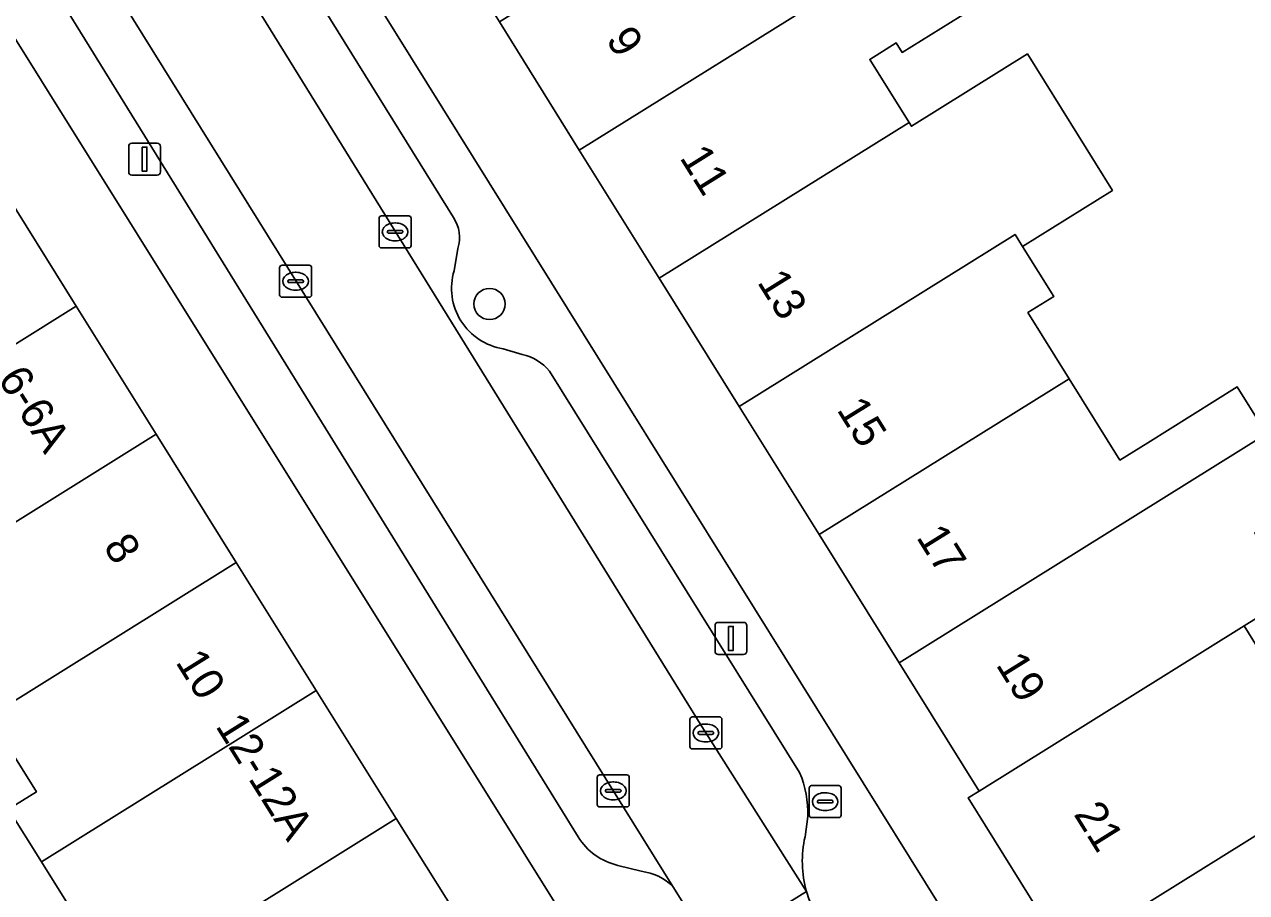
# Model space of a CAD drawing. Extents: x 159279 to 160377, y 384531 to 385888.
# Drawn here: x 159890.84 to 159929.07, y 385050.51 to 385077.67 of the extents above; entities that cross this region are included whole.
import ezdxf

# ---------------------------------------------------------------- set-up
doc = ezdxf.new("R2010")
doc.units = 0
for name, color, linetype in [('IMGEO_Boom', 7, 'Continuous'), ('IMGEO_Brandkraan', 7, 'Continuous'), ('IMGEO_Erf', 7, 'Continuous'), ('IMGEO_Kolk', 7, 'Continuous'), ('IMGEO_Lichtmast', 7, 'Continuous'), ('IMGEO_Pand', 7, 'Continuous'), ('IMGEO_Pand_nummerreeks', 7, 'Continuous'), ('IMGEO_Parkeervlak_open', 7, 'Continuous'), ('IMGEO_Rijbaan_lokaal_open', 7, 'Continuous'), ('IMGEO_Voetpad_open', 7, 'Continuous')]:
    doc.layers.add(name, color=color, linetype=linetype)

msp = doc.modelspace()

# ---------------------------------------------------------------- linework, layer by layer
at = {"layer": 'IMGEO_Boom'}
msp.add_circle((159905.388, 385068.924), 0.489, dxfattribs=at)
at = {"layer": 'IMGEO_Brandkraan'}
for p, q in [((159915.385, 385052.93), (159915.385, 385053.782)), ((159915.46, 385053.856), (159916.312, 385053.856)), ((159916.386, 385053.782), (159916.386, 385052.93)), ((159915.644, 385053.35), (159915.644, 385053.362)), ((159916.082, 385053.313), (159915.684, 385053.313)), ((159915.687, 385053.399), (159916.085, 385053.399)), ((159915.873, 385053.636), (159915.898, 385053.636)), ((159916.128, 385053.362), (159916.128, 385053.35)), ((159915.896, 385053.076), (159915.871, 385053.076)), ((159916.312, 385052.856), (159915.46, 385052.856))]:
    msp.add_line(p, q, dxfattribs=at)
for points in [[(159915.385, 385052.93), (159915.385, 385053.782)], [(159915.46, 385053.856), (159916.312, 385053.856)], [(159916.386, 385053.782), (159916.386, 385052.93)], [(159916.312, 385052.856), (159915.46, 385052.856)]]:
    msp.add_lwpolyline(points, dxfattribs=at)
for centre, radius, start, end in [((159915.462, 385053.78), 0.0765, 91.552, 178.448), ((159915.462, 385053.78), 0.0765, 91.552, 178.448), ((159916.31, 385053.78), 0.0765, 1.552, 88.448), ((159916.31, 385053.78), 0.0765, 1.552, 88.448), ((159915.684, 385053.359), 0.0403, 85.8775, 175.7526), ((159915.681, 385053.349), 0.0366, 178.938, 274.7102), ((159916.085, 385053.356), 0.043, 264.8664, 352.4533), ((159916.089, 385053.361), 0.0386, 1.7309, 96.639), ((159915.462, 385052.932), 0.0765, 181.552, 268.448), ((159915.462, 385052.932), 0.0765, 181.552, 268.448), ((159916.31, 385052.932), 0.0765, 271.552, 358.448), ((159916.31, 385052.932), 0.0765, 271.552, 358.448)]:
    msp.add_arc(centre, radius, start, end, dxfattribs=at)
for centre, major_axis, ratio, start_param, end_param in [((159915.872, 385053.356), (-0.387, 0.002), 0.722429, 4.712389, 7.853982), ((159915.897, 385053.356), (-0.39, 0.002), 0.717154, 1.570796, 4.712389)]:
    msp.add_ellipse(centre, major_axis=major_axis, ratio=ratio, start_param=start_param, end_param=end_param, dxfattribs=at)
at = {"layer": 'IMGEO_Erf'}
msp.add_lwpolyline([(159910.697, 385069.73), (159908.196, 385073.741), (159905.695, 385077.752), (159903.193, 385081.764), (159900.797, 385085.607), (159900.692, 385085.775), (159899.904, 385085.283), (159899.772, 385085.494), (159898.904, 385084.953), (159897.291, 385087.541), (159898.155, 385088.079), (159897.319, 385089.42), (159895.629, 385088.366), (159920.97, 385047.69), (159923.122, 385049.031), (159920.357, 385053.472), (159920.701, 385053.686), (159918.2, 385057.697), (159915.699, 385061.708), (159913.198, 385065.719)], close=True, dxfattribs=at)
for points in [[(159936.519, 385003.628), (159888.362, 385080.722), (159886.834, 385079.767), (159887.125, 385079.301), (159887.917, 385079.795), (159889.478, 385077.298), (159888.696, 385076.809), (159889.575, 385075.404), (159888.705, 385074.86), (159889.956, 385072.859), (159892.459, 385068.853), (159894.962, 385064.848), (159897.466, 385060.841), (159899.969, 385056.836), (159902.473, 385052.829), (159904.977, 385048.823)], [(159921.316, 385078.681), (159918.293, 385076.795), (159918.11, 385077.091), (159917.281, 385076.574), (159918.51, 385074.602), (159918.583, 385074.485), (159922.21, 385076.747), (159924.873, 385072.478), (159922.061, 385070.723), (159923.037, 385069.158), (159922.228, 385068.654), (159923.518, 385066.584), (159925.104, 385064.041), (159925.975, 385064.584), (159928.777, 385066.331), (159929.693, 385064.863)], [(159892.655, 385049.419), (159891.372, 385051.471), (159890.343, 385053.118), (159891.214, 385053.662), (159889.74, 385056.02), (159888.532, 385057.953), (159887.653, 385057.404), (159886.356, 385059.478), (159885.234, 385061.273), (159886.111, 385061.821), (159884.73, 385064.031), (159883.458, 385066.066), (159882.603, 385065.531), (159881.388, 385067.474), (159881.7, 385067.706), (159883.088, 385068.573), (159883.016, 385068.688), (159880.922, 385072.039), (159883.95, 385073.931), (159882.137, 385076.832), (159880.13, 385075.578), (159872.046, 385062.696), (159880.878, 385049.064)], [(159930.536, 385059.818), (159928.995, 385058.857), (159930.589, 385056.28)]]:
    msp.add_lwpolyline(points, dxfattribs=at)
at = {"layer": 'IMGEO_Kolk'}
for p, q in [((159902.009, 385071.68), (159902.861, 385071.68)), ((159901.934, 385070.754), (159901.934, 385071.606)), ((159902.422, 385071.46), (159902.447, 385071.46)), ((159902.935, 385071.606), (159902.935, 385070.754)), ((159902.193, 385071.174), (159902.193, 385071.186)), ((159902.631, 385071.137), (159902.233, 385071.137)), ((159902.236, 385071.223), (159902.634, 385071.223)), ((159902.445, 385070.9), (159902.42, 385070.9)), ((159902.677, 385071.186), (159902.677, 385071.174)), ((159902.861, 385070.68), (159902.009, 385070.68)), ((159898.898, 385070.135), (159899.75, 385070.135)), ((159898.823, 385069.209), (159898.823, 385070.061)), ((159899.311, 385069.915), (159899.336, 385069.915)), ((159899.824, 385070.061), (159899.824, 385069.209)), ((159899.082, 385069.629), (159899.082, 385069.641)), ((159899.52, 385069.592), (159899.122, 385069.592)), ((159899.125, 385069.678), (159899.523, 385069.678)), ((159899.334, 385069.355), (159899.309, 385069.355)), ((159899.566, 385069.641), (159899.566, 385069.629)), ((159899.75, 385069.135), (159898.898, 385069.135)), ((159911.729, 385056.004), (159912.581, 385056.004)), ((159911.654, 385055.078), (159911.654, 385055.93)), ((159912.142, 385055.784), (159912.167, 385055.784)), ((159912.655, 385055.93), (159912.655, 385055.078)), ((159911.913, 385055.498), (159911.913, 385055.51)), ((159912.351, 385055.461), (159911.953, 385055.461)), ((159911.956, 385055.547), (159912.354, 385055.547)), ((159912.165, 385055.224), (159912.14, 385055.224)), ((159912.397, 385055.51), (159912.397, 385055.498)), ((159912.581, 385055.004), (159911.729, 385055.004)), ((159908.758, 385053.266), (159908.758, 385054.118)), ((159908.833, 385054.192), (159909.685, 385054.192)), ((159909.759, 385054.118), (159909.759, 385053.266)), ((159909.017, 385053.686), (159909.017, 385053.698)), ((159909.455, 385053.649), (159909.057, 385053.649)), ((159909.06, 385053.735), (159909.458, 385053.735)), ((159909.246, 385053.972), (159909.271, 385053.972)), ((159909.501, 385053.698), (159909.501, 385053.686)), ((159909.269, 385053.412), (159909.244, 385053.412)), ((159909.685, 385053.192), (159908.833, 385053.192))]:
    msp.add_line(p, q, dxfattribs=at)
for points in [[(159902.009, 385071.68), (159902.861, 385071.68)], [(159901.934, 385070.754), (159901.934, 385071.606)], [(159902.935, 385071.606), (159902.935, 385070.754)], [(159902.861, 385070.68), (159902.009, 385070.68)], [(159898.898, 385070.135), (159899.75, 385070.135)], [(159898.823, 385069.209), (159898.823, 385070.061)], [(159899.824, 385070.061), (159899.824, 385069.209)], [(159899.75, 385069.135), (159898.898, 385069.135)], [(159911.729, 385056.004), (159912.581, 385056.004)], [(159911.654, 385055.078), (159911.654, 385055.93)], [(159912.655, 385055.93), (159912.655, 385055.078)], [(159912.581, 385055.004), (159911.729, 385055.004)], [(159908.758, 385053.266), (159908.758, 385054.118)], [(159908.833, 385054.192), (159909.685, 385054.192)], [(159909.759, 385054.118), (159909.759, 385053.266)], [(159909.685, 385053.192), (159908.833, 385053.192)]]:
    msp.add_lwpolyline(points, dxfattribs=at)
for centre, radius, start, end in [((159902.011, 385071.604), 0.0765, 91.552, 178.448), ((159902.011, 385071.604), 0.0765, 91.552, 178.448), ((159902.859, 385071.604), 0.0765, 1.552, 88.448), ((159902.859, 385071.604), 0.0765, 1.552, 88.448), ((159902.233, 385071.183), 0.0403, 85.8775, 175.7526), ((159902.23, 385071.173), 0.0366, 178.938, 274.7102), ((159902.634, 385071.18), 0.043, 264.8664, 352.4533), ((159902.638, 385071.185), 0.0386, 1.7309, 96.639), ((159902.011, 385070.756), 0.0765, 181.552, 268.448), ((159902.011, 385070.756), 0.0765, 181.552, 268.448), ((159902.859, 385070.756), 0.0765, 271.552, 358.448), ((159902.859, 385070.756), 0.0765, 271.552, 358.448), ((159898.9, 385070.059), 0.0765, 91.552, 178.448), ((159898.9, 385070.059), 0.0765, 91.552, 178.448), ((159899.748, 385070.059), 0.0765, 1.552, 88.448), ((159899.748, 385070.059), 0.0765, 1.552, 88.448), ((159899.122, 385069.638), 0.0403, 85.8775, 175.7526), ((159899.119, 385069.628), 0.0366, 178.938, 274.7102), ((159899.523, 385069.635), 0.043, 264.8664, 352.4533), ((159899.527, 385069.64), 0.0386, 1.7309, 96.639), ((159898.9, 385069.211), 0.0765, 181.552, 268.448), ((159898.9, 385069.211), 0.0765, 181.552, 268.448), ((159899.748, 385069.211), 0.0765, 271.552, 358.448), ((159899.748, 385069.211), 0.0765, 271.552, 358.448), ((159911.731, 385055.928), 0.0765, 91.552, 178.448), ((159911.731, 385055.928), 0.0765, 91.552, 178.448), ((159912.579, 385055.928), 0.0765, 1.552, 88.448), ((159912.579, 385055.928), 0.0765, 1.552, 88.448), ((159911.953, 385055.507), 0.0403, 85.8775, 175.7526), ((159911.95, 385055.497), 0.0366, 178.938, 274.7102), ((159912.354, 385055.504), 0.043, 264.8664, 352.4533), ((159912.358, 385055.509), 0.0386, 1.7309, 96.639), ((159911.731, 385055.08), 0.0765, 181.552, 268.448), ((159911.731, 385055.08), 0.0765, 181.552, 268.448), ((159912.579, 385055.08), 0.0765, 271.552, 358.448), ((159912.579, 385055.08), 0.0765, 271.552, 358.448), ((159908.835, 385054.116), 0.0765, 91.552, 178.448), ((159908.835, 385054.116), 0.0765, 91.552, 178.448), ((159909.683, 385054.116), 0.0765, 1.552, 88.448), ((159909.683, 385054.116), 0.0765, 1.552, 88.448), ((159909.057, 385053.695), 0.0403, 85.8775, 175.7526), ((159909.054, 385053.685), 0.0366, 178.938, 274.7102), ((159909.458, 385053.692), 0.043, 264.8664, 352.4533), ((159909.462, 385053.697), 0.0386, 1.7309, 96.639), ((159908.835, 385053.268), 0.0765, 181.552, 268.448), ((159908.835, 385053.268), 0.0765, 181.552, 268.448), ((159909.683, 385053.268), 0.0765, 271.552, 358.448), ((159909.683, 385053.268), 0.0765, 271.552, 358.448)]:
    msp.add_arc(centre, radius, start, end, dxfattribs=at)
for centre, major_axis, ratio, start_param, end_param in [((159902.421, 385071.18), (-0.387, 0.002), 0.722429, 4.712389, 7.853982), ((159902.446, 385071.18), (-0.39, 0.002), 0.717154, 1.570796, 4.712389), ((159899.31, 385069.635), (-0.387, 0.002), 0.722429, 4.712389, 7.853982), ((159899.335, 385069.635), (-0.39, 0.002), 0.717154, 1.570796, 4.712389), ((159912.141, 385055.504), (-0.387, 0.002), 0.722429, 4.712389, 7.853982), ((159912.166, 385055.504), (-0.39, 0.002), 0.717154, 1.570796, 4.712389), ((159909.245, 385053.692), (-0.387, 0.002), 0.722429, 4.712389, 7.853982), ((159909.27, 385053.692), (-0.39, 0.002), 0.717154, 1.570796, 4.712389)]:
    msp.add_ellipse(centre, major_axis=major_axis, ratio=ratio, start_param=start_param, end_param=end_param, dxfattribs=at)
at = {"layer": 'IMGEO_Lichtmast'}
for p, q in [((159894.202, 385073.956), (159894.992, 385073.956)), ((159894.992, 385073.956), (159894.202, 385073.956)), ((159894.102, 385073.056), (159894.102, 385073.856)), ((159894.102, 385073.856), (159894.102, 385073.056)), ((159895.092, 385073.856), (159895.092, 385073.056)), ((159895.092, 385073.056), (159895.092, 385073.856)), ((159894.992, 385072.956), (159894.202, 385072.956)), ((159894.202, 385072.956), (159894.992, 385072.956)), ((159912.442, 385058.063), (159912.442, 385058.863)), ((159912.442, 385058.863), (159912.442, 385058.063)), ((159912.542, 385058.963), (159913.332, 385058.963)), ((159913.332, 385058.963), (159912.542, 385058.963)), ((159913.432, 385058.863), (159913.432, 385058.063)), ((159913.432, 385058.063), (159913.432, 385058.863)), ((159913.332, 385057.963), (159912.542, 385057.963)), ((159912.542, 385057.963), (159913.332, 385057.963))]:
    msp.add_line(p, q, dxfattribs=at)
for points in [[(159894.522, 385073.831), (159894.672, 385073.831), (159894.672, 385073.081), (159894.522, 385073.081), (159894.522, 385073.831)], [(159912.862, 385058.838), (159913.012, 385058.838), (159913.012, 385058.088), (159912.862, 385058.088), (159912.862, 385058.838)]]:
    msp.add_lwpolyline(points, dxfattribs=at)
for centre, start, end in [((159894.202, 385073.856), 90, 180), ((159894.202, 385073.856), 90, 180), ((159894.992, 385073.856), 0, 90), ((159894.992, 385073.856), 360, 90), ((159894.202, 385073.056), 180, 270), ((159894.202, 385073.056), 180, 270), ((159894.992, 385073.056), 270, 0), ((159894.992, 385073.056), 270, 0), ((159912.542, 385058.863), 90, 180), ((159912.542, 385058.863), 90, 180), ((159913.332, 385058.863), 0, 90), ((159913.332, 385058.863), 360, 90), ((159912.542, 385058.063), 180, 270), ((159912.542, 385058.063), 180, 270), ((159913.332, 385058.063), 270, 0), ((159913.332, 385058.063), 270, 0)]:
    msp.add_arc(centre, 0.1, start, end, dxfattribs=at)
at = {"layer": 'IMGEO_Pand'}
for points in [[(159905.695, 385077.752), (159908.196, 385073.741), (159916.838, 385079.13), (159915.82, 385080.763), (159915, 385080.252), (159913.517, 385082.63)], [(159916.838, 385079.13), (159908.196, 385073.741), (159910.697, 385069.73), (159918.51, 385074.602), (159917.281, 385076.574), (159918.11, 385077.091), (159918.293, 385076.795), (159921.316, 385078.681), (159921.132, 385078.976), (159921.083, 385079.055), (159919.86, 385081.015)], [(159921.826, 385071.099), (159922.061, 385070.723), (159924.873, 385072.478), (159922.21, 385076.747), (159918.583, 385074.485), (159918.51, 385074.602), (159910.697, 385069.73), (159913.198, 385065.719)], [(159892.459, 385068.853), (159889.956, 385072.859), (159883.088, 385068.573), (159881.7, 385067.706), (159881.388, 385067.474), (159882.603, 385065.531), (159883.458, 385066.066), (159884.73, 385064.031)], [(159923.518, 385066.584), (159922.228, 385068.654), (159923.037, 385069.158), (159922.061, 385070.723), (159921.826, 385071.099), (159913.198, 385065.719), (159915.699, 385061.708)], [(159894.962, 385064.848), (159892.459, 385068.853), (159884.73, 385064.031), (159886.111, 385061.821), (159885.234, 385061.273), (159886.356, 385059.478)], [(159929.693, 385064.863), (159928.777, 385066.331), (159925.975, 385064.584), (159925.104, 385064.041), (159923.518, 385066.584), (159915.699, 385061.708), (159918.2, 385057.697)], [(159886.356, 385059.478), (159887.653, 385057.404), (159888.532, 385057.953), (159889.74, 385056.02), (159897.466, 385060.841), (159894.962, 385064.848)], [(159930.536, 385059.818), (159929.322, 385061.766), (159930.979, 385062.8), (159929.693, 385064.863), (159918.2, 385057.697), (159920.701, 385053.686), (159928.995, 385058.857)], [(159899.969, 385056.836), (159897.466, 385060.841), (159889.74, 385056.02), (159891.214, 385053.662), (159890.343, 385053.118), (159891.372, 385051.471)], [(159932.027, 385053.956), (159931.577, 385054.683), (159930.589, 385056.28), (159928.995, 385058.857), (159920.701, 385053.686), (159920.357, 385053.472), (159923.122, 385049.031), (159923.401, 385048.583), (159931.872, 385053.86)], [(159891.372, 385051.471), (159892.655, 385049.419), (159893.516, 385049.958), (159894.738, 385048.003), (159902.473, 385052.829), (159899.969, 385056.836)], [(159932.705, 385050.93), (159933.567, 385051.467), (159936.373, 385053.215), (159935.086, 385055.282), (159934.826, 385055.699), (159932.027, 385053.956), (159931.872, 385053.86), (159923.401, 385048.583), (159923.69, 385048.119), (159926.445, 385043.693), (159926.789, 385043.908), (159934.649, 385048.811), (159934.454, 385049.124), (159934.004, 385048.844)], [(159904.977, 385048.823), (159902.473, 385052.829), (159894.738, 385048.003), (159896.192, 385045.676), (159895.28, 385045.106), (159896.329, 385043.428)]]:
    msp.add_lwpolyline(points, close=True, dxfattribs=at)
at = {"layer": 'IMGEO_Parkeervlak_open'}
for points in [[(159893.204, 385086.133), (159912.027, 385055.709), (159915.303, 385050.54)], [(159904.257, 385071.628), (159896.191, 385084.632)], [(159911.126, 385050.697), (159890.937, 385083.152)], [(159891.126, 385079.816), (159908.159, 385052.253)], [(159904.283, 385069.964), (159904.392, 385070.664)], [(159906.412, 385067.34), (159905.814, 385067.525)], [(159915.088, 385054.264), (159907.267, 385066.826)], [(159915.256, 385052.259), (159915.34, 385052.894)], [(159909.398, 385051.361), (159910.136, 385051.177)]]:
    msp.add_lwpolyline(points, dxfattribs=at)
for centre, radius, start, end in [((159903.385, 385071.014), 1.066, 340.8059, 35.138), ((159906.11, 385069.411), 1.909, 163.1441, 261.0902), ((159906.086, 385065.83), 1.545, 40.1486, 77.8253), ((159912.084, 385053.003), 3.258, 358.0797, 22.7654), ((159909.858, 385053.306), 1.998, 211.7932, 256.7039), ((159918.662, 385051.492), 3.491, 167.3095, 195.8228), ((159909.927, 385049.486), 1.704, 45.3002, 82.9671)]:
    msp.add_arc(centre, radius, start, end, dxfattribs=at)
at = {"layer": 'IMGEO_Rijbaan_lokaal_open'}
for points in [[(159911.126, 385050.697), (159912.358, 385048.721), (159915.303, 385050.54), (159912.027, 385055.709), (159893.204, 385086.133), (159890.162, 385084.183), (159890.776, 385083.377), (159890.937, 385083.152)], [(159915.386, 385050.286), (159915.303, 385050.54), (159912.358, 385048.721), (159914.634, 385045.069), (159917.496, 385046.88)]]:
    msp.add_lwpolyline(points, close=True, dxfattribs=at)
at = {"layer": 'IMGEO_Voetpad_open'}
for points in [[(159872.121, 385097.552), (159872.011, 385097.626), (159871.548, 385097.911), (159871.061, 385098.154), (159869.401, 385095.52), (159877.92, 385089.911), (159882.977, 385086.545), (159886.159, 385084.445), (159887.093, 385082.754), (159888.362, 385080.722), (159936.519, 385003.628), (159934.035, 385000), (159926.157, 384988.496), (159925.515, 384987.558), (159922.318, 384982.839), (159919.321, 384978.411), (159922.705, 384976.055), (159935.802, 384995.298)], [(159925.436, 384938.175), (159925.666, 384938.022), (159928.099, 384938.394), (159928.311, 384938.426), (159934.331, 384939.346), (159933.907, 384942.703), (159933.789, 384943.295), (159932.965, 384948.873), (159932.16, 384954.319), (159931.355, 384959.765), (159930.173, 384967.765), (159934.703, 384974.467), (159937.871, 384979.153), (159938.432, 384979.992), (159951.23, 384999.12), (159950.682, 385000), (159921.539, 385046.778), (159920.97, 385047.69), (159895.629, 385088.366), (159894.998, 385089.378)], [(159896.191, 385084.632), (159904.257, 385071.628)], [(159908.159, 385052.253), (159891.126, 385079.816)], [(159904.392, 385070.664), (159904.283, 385069.964)], [(159905.814, 385067.525), (159906.412, 385067.34)], [(159907.267, 385066.826), (159915.088, 385054.264)], [(159915.34, 385052.894), (159915.256, 385052.259)], [(159910.136, 385051.177), (159909.398, 385051.361)], [(159914.634, 385045.069), (159912.358, 385048.721), (159911.126, 385050.697)], [(159915.303, 385050.54), (159915.386, 385050.286), (159917.496, 385046.88)]]:
    msp.add_lwpolyline(points, dxfattribs=at)
for centre, radius, start, end in [((159903.385, 385071.014), 1.066, 340.8059, 35.138), ((159906.11, 385069.411), 1.909, 163.1441, 261.0902), ((159906.086, 385065.83), 1.545, 40.1486, 77.8253), ((159912.084, 385053.003), 3.258, 358.0797, 22.7654), ((159909.858, 385053.306), 1.998, 211.7932, 256.7039), ((159918.662, 385051.492), 3.491, 167.3095, 195.8228), ((159909.927, 385049.486), 1.704, 45.3002, 82.9671)]:
    msp.add_arc(centre, radius, start, end, dxfattribs=at)

# ---------------------------------------------------------------- texts
at = {"layer": 'IMGEO_Pand_nummerreeks'}
for s, rotation, p in [('9', 301.9452, (159909.01, 385077.199)), ('11', 301.9479, (159911.315, 385073.503)), ('13', 301.9479, (159913.742, 385069.609)), ('6-6A', 302.0379, (159889.989, 385066.583)), ('15', 301.9479, (159916.23, 385065.619)), ('8', 302.0032, (159893.289, 385061.337)), ('17', 301.9452, (159918.718, 385061.628)), ('10', 302.0032, (159895.548, 385057.721)), ('19', 301.9479, (159921.206, 385057.638)), ('12-12A', 302.0015, (159896.799, 385055.72)), ('21', 301.9021, (159923.641, 385052.964))]:
    msp.add_text(s, height=1, rotation=rotation, dxfattribs=at).set_placement(p)

doc.saveas('drawing.dxf')
